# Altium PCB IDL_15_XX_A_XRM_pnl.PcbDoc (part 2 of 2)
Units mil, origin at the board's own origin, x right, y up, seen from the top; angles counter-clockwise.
Board outline 6130 x 3614.17 mil, 6 copper layers (Top Layer - SIG1, Layer 2 - GND1, Layer 3 - SIG2, Layer 4 - SIG3, Layer 5 - GND2, Bottom Layer - SIG4), stack 49.592 mil thick; 576 components, 385 nets, 1280 pads, 0 vias.
Unrouted connection lines stored in the file: 895.
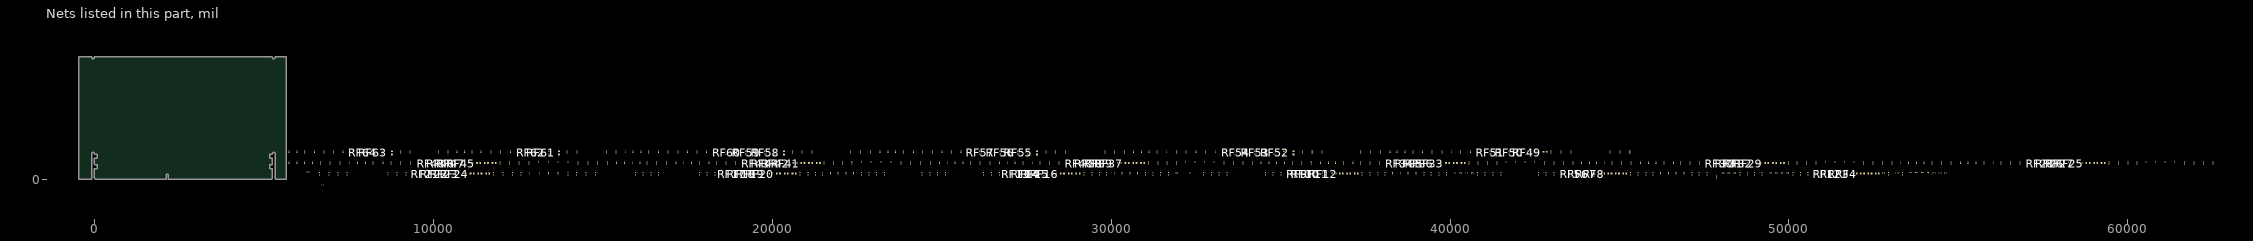
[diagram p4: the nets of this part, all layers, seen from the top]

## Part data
C1 C2 C3 C4 C13 C14 C15 C16 C17 C18 C19 C20 C21 C22 C23 C24 C33 C34 C35 C36 C37 C38 C39 C40 C41 C42 C43 C44 C53 C54 C55 C56 C57 C58 C59 C60 C61 C62 C63 C64 C73 C74 C75 C76 C77 C78 C79 C80 C81 C82 C83 C84 C93 C94 C95 C96 C97 C98 C99 C100 C101 C102 C103 C104 C113 C114 C115 C116 C117 C118 C119 C120 C121 C122 C123 C124 C133 C134 C135 C136 C137 C138 C139 C140 C141 C142 C143 C144 C153 C154 C155 C156 C157 C158 C159 C160 C161 C162 C163 C164 C173 C174 C175 C176 C177 C178 C179 C180 C181 C182 C183 C184 C193 C194 C195 C196 C197 C198 C199 C200 C201 C202 C203 C204 C213 C214 C215 C216 C217 C218 C219 C220 C221 C222 C223 C224 C233 C234 C235 C236 C237 C238 C239 C240 C241 C242 C243 C250 C251 C252 C253 C254 C255 C256 C257 C258 C265 C266 C267 C268 C269 C270 C271 C272 C273 C280 C281 C282 C283 C284 C285 C286 C287 C288 C295 C296 C297 C298 C299 C300 C301 C302 C307 C308 C309 C310 C311 C312 C317 C318 C319 C320: library part CAPCC0603_1_10N_50VX7R, "Capacitor chip ceramic 0603 50V X7R"
C5 C6 C7 C8 C25 C26 C27 C28 C45 C46 C47 C48 C65 C66 C67 C68 C85 C86 C87 C88 C105 C106 C107 C108 C125 C126 C127 C128 C145 C146 C147 C148 C165 C166 C167 C168 C185 C186 C187 C188 C205 C206 C207 C208 C225 C226 C227 C228 C244 C245 C246 C259 C260 C261 C274 C275 C276 C289 C290 C291 C303 C304 C313 C314: library part CAPCC0402_1_100N_50VX7R, "Capacitor chip ceramic 0402 50V X7R"
C9 C10 C11 C12 C29 C30 C31 C32 C49 C50 C51 C52 C69 C70 C71 C72 C89 C90 C91 C92 C109 C110 C111 C112 C129 C130 C131 C132 C149 C150 C151 C152 C169 C170 C171 C172 C189 C190 C191 C192 C209 C210 C211 C212 C229 C230 C231 C232 C247 C248 C249 C262 C263 C264 C277 C278 C279 C292 C293 C294 C305 C306 C315 C316: library part CAPCC0603_2_1U_50VX7R, "Capacitor chip ceramic 0603 50V X7R"
L1 L2 L3 L4 L9 L10 L11 L12 L17 L18 L19 L20 L25 L26 L27 L28 L33 L34 L35 L36 L41 L42 L43 L44 L49 L50 L51 L52 L57 L58 L59 L60 L65 L66 L67 L68 L73 L74 L75 L76 L81 L82 L83 L84 L89 L90 L91 L92 L97 L98 L99 L103 L104 L105 L109 L110 L111 L115 L116 L117 L121 L122 L125 L126: library part IND1008-1.5U_0.33A, "Chip inductor 1008 0.33A 2.3R"
L5 L6 L7 L8 L13 L14 L15 L16 L21 L22 L23 L24 L29 L30 L31 L32 L37 L38 L39 L40 L45 L46 L47 L48 L53 L54 L55 L56 L61 L62 L63 L64 L69 L70 L71 L72 L77 L78 L79 L80 L85 L86 L87 L88 L93 L94 L95 L96 L100 L101 L102 L106 L107 L108 L112 L113 L114 L118 L119 L120 L123 L124 L127 L128: library part IND0402-10.5N_1.0A, "Chip inductor 0402 1.0A 100mR"
R1 R2 R3 R4 R5 R6 R7 R8 R9 R10 R11 R12 R13 R14 R15 R16 R17 R18 R19 R20 R21 R22 R23 R24 R25 R26 R27 R28 R29 R30 R31 R32 R33 R34 R35 R36 R37 R38 R39 R40 R41 R42 R43 R44 R45 R46 R47 R48 R49 R50 R51 R52 R53 R54 R55 R56 R57 R58 R59 R60 R61 R62 R63 R64: library part RES0402-0-49.9R-1%100PPM, "Chip Resistor 0402 62.5mW 1% 100ppm"
RF1 RF2 RF3 RF4 RF5 RF6 RF7 RF8 RF9 RF10 RF11 RF12 RF13 RF14 RF15 RF16 RF17 RF18 RF19 RF20 RF21 RF22 RF23 RF24 RF25 RF26 RF27 RF28 RF29 RF30 RF31 RF32 RF33 RF34 RF35 RF36 RF37 RF38 RF39 RF40 RF41 RF42 RF43 RF44 RF45 RF46 RF47 RF48 RF49 RF50 RF51 RF52 RF53 RF54 RF55 RF56 RF57 RF58 RF59 RF60 RF61 RF62 RF63 RF64: "Monolithic Amplifier 50MHz - 4GHz, 0.75NF"

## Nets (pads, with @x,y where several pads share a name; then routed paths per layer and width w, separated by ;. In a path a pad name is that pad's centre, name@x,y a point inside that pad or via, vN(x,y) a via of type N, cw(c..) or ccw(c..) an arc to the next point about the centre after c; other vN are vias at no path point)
GND: C1.2 C2.2 C3.2 C4.2 C5.2 C6.2 C7.2 C8.2 C9.2 C10.2 C11.2 C12.2 C21.2 C22.2 C23.2 C24.2 C25.2 C26.2 C27.2 C28.2 C29.2 C30.2 C31.2 C32.2 C41.2 C42.2 C43.2 C44.2 C45.2 C46.2 C47.2 C48.2 C49.2 C50.2 C51.2 C52.2 C61.2 C62.2 C63.2 C64.2 C65.2 C66.2 C67.2 C68.2 C69.2 C70.2 C71.2 C72.2 C81.2 C82.2 C83.2 C84.2 C85.2 C86.2 C87.2 C88.2 C89.2 C90.2 C91.2 C92.2 C101.2 C102.2 C103.2 C104.2 C105.2 C106.2 C107.2 C108.2 C109.2 C110.2 C111.2 C112.2 C121.2 C122.2 C123.2 C124.2 C125.2 C126.2 C127.2 C128.2 C129.2 C130.2 C131.2 C132.2 C141.2 C142.2 C143.2 C144.2 C145.2 C146.2 C147.2 C148.2 C149.2 C150.2 C151.2 C152.2 C161.2 C162.2 C163.2 C164.2 C165.2 C166.2 C167.2 C168.2 C169.2 C170.2 C171.2 C172.2 C181.2 C182.2 C183.2 C184.2 C185.2 C186.2 C187.2 C188.2 C189.2 C190.2 C191.2 C192.2 C201.2 C202.2 C203.2 C204.2 C205.2 C206.2 C207.2 C208.2 C209.2 C210.2 C211.2 C212.2 C221.2 C222.2 C223.2 C224.2 C225.2 C226.2 C227.2 C228.2 C229.2 C230.2 C231.2 C232.2 C241.2 C242.2 C243.2 C244.2 C245.2 C246.2 C247.2 C248.2 C249.2 C256.2 C257.2 C258.2 C259.2 C260.2 C261.2 C262.2 C263.2 C264.2 C271.2 C272.2 C273.2 C274.2 C275.2 C276.2 C277.2 C278.2 C279.2 C286.2 C287.2 C288.2 C289.2 C290.2 C291.2 C292.2 C293.2 C294.2 C301.2 C302.2 C303.2 C304.2 C305.2 C306.2 C311.2 C312.2 C313.2 C314.2 C315.2 C316.2 R1.1 R2.1 R3.1 R4.1 R5.1 R6.1 R7.1 R8.1 R9.1 R10.1 R11.1 R12.1 R13.1 R14.1 R15.1 R16.1 R17.1 R18.1 R19.1 R20.1 R21.1 R22.1 R23.1 R24.1 R25.1 R26.1 R27.1 R28.1 R29.1 R30.1 R31.1 R32.1 R33.1 R34.1 R35.1 R36.1 R37.1 R38.1 R39.1 R40.1 R41.1 R42.1 R43.1 R44.1 R45.1 R46.1 R47.1 R48.1 R49.1 R50.1 R51.1 R52.1 R53.1 R54.1 R55.1 R56.1 R57.1 R58.1 R59.1 R60.1 R61.1 R62.1 R63.1 R64.1 RF1.2 RF1.4 RF2.2 RF2.4 RF3.2 RF3.4 RF4.2 RF4.4 RF5.2 RF5.4 RF6.2 RF6.4 RF7.2 RF7.4 RF8.2 RF8.4 RF9.2 RF9.4 RF10.2 RF10.4 RF11.2 RF11.4 RF12.2 RF12.4 RF13.2 RF13.4 RF14.2 RF14.4 RF15.2 RF15.4 RF16.2 RF16.4 RF17.2 RF17.4 RF18.2 RF18.4 RF19.2 RF19.4 RF20.2 RF20.4 RF21.2 RF21.4 RF22.2 RF22.4 RF23.2 RF23.4 RF24.2 RF24.4 RF25.2 RF25.4 RF26.2 RF26.4 RF27.2 RF27.4 RF28.2 RF28.4 RF29.2 RF29.4 RF30.2 RF30.4 RF31.2 RF31.4 RF32.2 RF32.4 RF33.2 RF33.4 RF34.2 RF34.4 RF35.2 RF35.4 RF36.2 RF36.4 RF37.2 RF37.4 RF38.2 RF38.4 RF39.2 RF39.4 RF40.2 RF40.4 RF41.2 RF41.4 RF42.2 RF42.4 RF43.2 RF43.4 RF44.2 RF44.4 RF45.2 RF45.4 RF46.2 RF46.4 RF47.2 RF47.4 RF48.2 RF48.4 RF49.2 RF49.4 RF50.2 RF50.4 RF51.2 RF51.4 RF52.2 RF52.4 RF53.2 RF53.4 RF54.2 RF54.4 RF55.2 RF55.4 RF56.2 RF56.4 RF57.2 RF57.4 RF58.2 RF58.4 RF59.2 RF59.4 RF60.2 RF60.4 RF61.2 RF61.4 RF62.2 RF62.4 RF63.2 RF63.4 RF64.2 RF64.4
NetC1_1: C1.1 C5.1 C9.1 L1.2
NetC2_1: C2.1 C6.1 C10.1 L2.2
NetC3_1: C3.1 C7.1 C11.1 L3.2
NetC4_1: C4.1 C8.1 C12.1 L4.2
NetC13_1: C13.1 L1.1 RF1.1
NetC13_2: C13.2 L5.1
NetC14_1: C14.1 L2.1 RF2.1
NetC14_2: C14.2 L6.1
NetC15_1: C15.1 L3.1 RF3.1
NetC15_2: C15.2 L7.1
NetC16_1: C16.1 L4.1 RF4.1
NetC16_2: C16.2 L8.1
NetC17_2: C17.2 RF1.3
NetC18_2: C18.2 RF2.3
NetC19_2: C19.2 RF3.3
NetC20_2: C20.2 RF4.3
NetC21_1: C21.1 C25.1 C29.1 L9.2
NetC22_1: C22.1 C26.1 C30.1 L10.2
NetC23_1: C23.1 C27.1 C31.1 L11.2
NetC24_1: C24.1 C28.1 C32.1 L12.2
NetC33_1: C33.1 L9.1 RF5.1
NetC33_2: C33.2 L13.1
NetC34_1: C34.1 L10.1 RF6.1
NetC34_2: C34.2 L14.1
NetC35_1: C35.1 L11.1 RF7.1
NetC35_2: C35.2 L15.1
NetC36_1: C36.1 L12.1 RF8.1
NetC36_2: C36.2 L16.1
NetC37_2: C37.2 RF5.3
NetC38_2: C38.2 RF6.3
NetC39_2: C39.2 RF7.3
NetC40_2: C40.2 RF8.3
NetC41_1: C41.1 C45.1 C49.1 L17.2
NetC42_1: C42.1 C46.1 C50.1 L18.2
NetC43_1: C43.1 C47.1 C51.1 L19.2
NetC44_1: C44.1 C48.1 C52.1 L20.2
NetC53_1: C53.1 L17.1 RF9.1
NetC53_2: C53.2 L21.1
NetC54_1: C54.1 L18.1 RF10.1
NetC54_2: C54.2 L22.1
NetC55_1: C55.1 L19.1 RF11.1
NetC55_2: C55.2 L23.1
NetC56_1: C56.1 L20.1 RF12.1
NetC56_2: C56.2 L24.1
NetC57_2: C57.2 RF9.3
NetC58_2: C58.2 RF10.3
NetC59_2: C59.2 RF11.3
NetC60_2: C60.2 RF12.3
NetC61_1: C61.1 C65.1 C69.1 L25.2
NetC62_1: C62.1 C66.1 C70.1 L26.2
NetC63_1: C63.1 C67.1 C71.1 L27.2
NetC64_1: C64.1 C68.1 C72.1 L28.2
NetC73_1: C73.1 L25.1 RF13.1
NetC73_2: C73.2 L29.1
NetC74_1: C74.1 L26.1 RF14.1
NetC74_2: C74.2 L30.1
NetC75_1: C75.1 L27.1 RF15.1
NetC75_2: C75.2 L31.1
NetC76_1: C76.1 L28.1 RF16.1
NetC76_2: C76.2 L32.1
NetC77_2: C77.2 RF13.3
NetC78_2: C78.2 RF14.3
NetC79_2: C79.2 RF15.3
NetC80_2: C80.2 RF16.3
NetC81_1: C81.1 C85.1 C89.1 L33.2
NetC82_1: C82.1 C86.1 C90.1 L34.2
NetC83_1: C83.1 C87.1 C91.1 L35.2
NetC84_1: C84.1 C88.1 C92.1 L36.2
NetC93_1: C93.1 L33.1 RF17.1
NetC93_2: C93.2 L37.1
NetC94_1: C94.1 L34.1 RF18.1
NetC94_2: C94.2 L38.1
NetC95_1: C95.1 L35.1 RF19.1
NetC95_2: C95.2 L39.1
NetC96_1: C96.1 L36.1 RF20.1
NetC96_2: C96.2 L40.1
NetC97_2: C97.2 RF17.3
NetC98_2: C98.2 RF18.3
NetC99_2: C99.2 RF19.3
NetC100_2: C100.2 RF20.3
NetC101_1: C101.1 C105.1 C109.1 L41.2
NetC102_1: C102.1 C106.1 C110.1 L42.2
NetC103_1: C103.1 C107.1 C111.1 L43.2
NetC104_1: C104.1 C108.1 C112.1 L44.2
NetC113_1: C113.1 L41.1 RF21.1
NetC113_2: C113.2 L45.1
NetC114_1: C114.1 L42.1 RF22.1
NetC114_2: C114.2 L46.1
NetC115_1: C115.1 L43.1 RF23.1
NetC115_2: C115.2 L47.1
NetC116_1: C116.1 L44.1 RF24.1
NetC116_2: C116.2 L48.1
NetC117_2: C117.2 RF21.3
NetC118_2: C118.2 RF22.3
NetC119_2: C119.2 RF23.3
NetC120_2: C120.2 RF24.3
NetC121_1: C121.1 C125.1 C129.1 L49.2
NetC122_1: C122.1 C126.1 C130.1 L50.2
NetC123_1: C123.1 C127.1 C131.1 L51.2
NetC124_1: C124.1 C128.1 C132.1 L52.2
NetC133_1: C133.1 L49.1 RF25.1
NetC133_2: C133.2 L53.1
NetC134_1: C134.1 L50.1 RF26.1
NetC134_2: C134.2 L54.1
NetC135_1: C135.1 L51.1 RF27.1
NetC135_2: C135.2 L55.1
NetC136_1: C136.1 L52.1 RF28.1
NetC136_2: C136.2 L56.1
NetC137_2: C137.2 RF25.3
NetC138_2: C138.2 RF26.3
NetC139_2: C139.2 RF27.3
NetC140_2: C140.2 RF28.3
NetC141_1: C141.1 C145.1 C149.1 L57.2
NetC142_1: C142.1 C146.1 C150.1 L58.2
NetC143_1: C143.1 C147.1 C151.1 L59.2
NetC144_1: C144.1 C148.1 C152.1 L60.2
NetC153_1: C153.1 L57.1 RF29.1
NetC153_2: C153.2 L61.1
NetC154_1: C154.1 L58.1 RF30.1
NetC154_2: C154.2 L62.1
NetC155_1: C155.1 L59.1 RF31.1
NetC155_2: C155.2 L63.1
NetC156_1: C156.1 L60.1 RF32.1
NetC156_2: C156.2 L64.1
NetC157_2: C157.2 RF29.3
NetC158_2: C158.2 RF30.3
NetC159_2: C159.2 RF31.3
NetC160_2: C160.2 RF32.3
NetC161_1: C161.1 C165.1 C169.1 L65.2
NetC162_1: C162.1 C166.1 C170.1 L66.2
NetC163_1: C163.1 C167.1 C171.1 L67.2
NetC164_1: C164.1 C168.1 C172.1 L68.2
NetC173_1: C173.1 L65.1 RF33.1
NetC173_2: C173.2 L69.1
NetC174_1: C174.1 L66.1 RF34.1
NetC174_2: C174.2 L70.1
NetC175_1: C175.1 L67.1 RF35.1
NetC175_2: C175.2 L71.1
NetC176_1: C176.1 L68.1 RF36.1
NetC176_2: C176.2 L72.1
NetC177_2: C177.2 RF33.3
NetC178_2: C178.2 RF34.3
NetC179_2: C179.2 RF35.3
NetC180_2: C180.2 RF36.3
NetC181_1: C181.1 C185.1 C189.1 L73.2
NetC182_1: C182.1 C186.1 C190.1 L74.2
NetC183_1: C183.1 C187.1 C191.1 L75.2
NetC184_1: C184.1 C188.1 C192.1 L76.2
NetC193_1: C193.1 L73.1 RF37.1
NetC193_2: C193.2 L77.1
NetC194_1: C194.1 L74.1 RF38.1
NetC194_2: C194.2 L78.1
NetC195_1: C195.1 L75.1 RF39.1
NetC195_2: C195.2 L79.1
NetC196_1: C196.1 L76.1 RF40.1
NetC196_2: C196.2 L80.1
NetC197_2: C197.2 RF37.3
NetC198_2: C198.2 RF38.3
NetC199_2: C199.2 RF39.3
NetC200_2: C200.2 RF40.3
NetC201_1: C201.1 C205.1 C209.1 L81.2
NetC202_1: C202.1 C206.1 C210.1 L82.2
NetC203_1: C203.1 C207.1 C211.1 L83.2
NetC204_1: C204.1 C208.1 C212.1 L84.2
NetC213_1: C213.1 L81.1 RF41.1
NetC213_2: C213.2 L85.1
NetC214_1: C214.1 L82.1 RF42.1
NetC214_2: C214.2 L86.1
NetC215_1: C215.1 L83.1 RF43.1
NetC215_2: C215.2 L87.1
NetC216_1: C216.1 L84.1 RF44.1
NetC216_2: C216.2 L88.1
NetC217_2: C217.2 RF41.3
NetC218_2: C218.2 RF42.3
NetC219_2: C219.2 RF43.3
NetC220_2: C220.2 RF44.3
NetC221_1: C221.1 C225.1 C229.1 L89.2
NetC222_1: C222.1 C226.1 C230.1 L90.2
NetC223_1: C223.1 C227.1 C231.1 L91.2
NetC224_1: C224.1 C228.1 C232.1 L92.2
NetC233_1: C233.1 L89.1 RF45.1
NetC233_2: C233.2 L93.1
NetC234_1: C234.1 L90.1 RF46.1
NetC234_2: C234.2 L94.1
NetC235_1: C235.1 L91.1 RF47.1
NetC235_2: C235.2 L95.1
NetC236_1: C236.1 L92.1 RF48.1
NetC236_2: C236.2 L96.1
NetC237_2: C237.2 RF45.3
NetC238_2: C238.2 RF46.3
NetC239_2: C239.2 RF47.3
NetC240_2: C240.2 RF48.3
NetC241_1: C241.1 C244.1 C247.1 L97.2
NetC242_1: C242.1 C245.1 C248.1 L98.2
NetC243_1: C243.1 C246.1 C249.1 L99.2
NetC250_1: C250.1 L97.1 RF49.1
NetC250_2: C250.2 L100.1
NetC251_1: C251.1 L98.1 RF50.1
NetC251_2: C251.2 L101.1
NetC252_2: C252.2 RF49.3
NetC253_1: C253.1 L99.1 RF51.1
NetC253_2: C253.2 L102.1
NetC254_2: C254.2 RF50.3
NetC255_2: C255.2 RF51.3
NetC256_1: C256.1 C259.1 C262.1 L103.2
NetC257_1: C257.1 C260.1 C263.1 L104.2
NetC258_1: C258.1 C261.1 C264.1 L105.2
NetC265_1: C265.1 L103.1 RF52.1
NetC265_2: C265.2 L106.1
NetC266_1: C266.1 L104.1 RF53.1
NetC266_2: C266.2 L107.1
NetC267_2: C267.2 RF52.3
NetC268_1: C268.1 L105.1 RF54.1
NetC268_2: C268.2 L108.1
NetC269_2: C269.2 RF53.3
NetC270_2: C270.2 RF54.3
NetC271_1: C271.1 C274.1 C277.1 L109.2
NetC272_1: C272.1 C275.1 C278.1 L110.2
NetC273_1: C273.1 C276.1 C279.1 L111.2
NetC280_1: C280.1 L109.1 RF55.1
NetC280_2: C280.2 L112.1
NetC281_1: C281.1 L110.1 RF56.1
NetC281_2: C281.2 L113.1
NetC282_2: C282.2 RF55.3
NetC283_1: C283.1 L111.1 RF57.1
NetC283_2: C283.2 L114.1
NetC284_2: C284.2 RF56.3
NetC285_2: C285.2 RF57.3
NetC286_1: C286.1 C289.1 C292.1 L115.2
NetC287_1: C287.1 C290.1 C293.1 L116.2
NetC288_1: C288.1 C291.1 C294.1 L117.2
NetC295_1: C295.1 L115.1 RF58.1
NetC295_2: C295.2 L118.1
NetC296_1: C296.1 L116.1 RF59.1
NetC296_2: C296.2 L119.1
NetC297_2: C297.2 RF58.3
NetC298_1: C298.1 L117.1 RF60.1
NetC298_2: C298.2 L120.1
NetC299_2: C299.2 RF59.3
NetC300_2: C300.2 RF60.3
NetC301_1: C301.1 C303.1 C305.1 L121.2
NetC302_1: C302.1 C304.1 C306.1 L122.2
NetC307_1: C307.1 L121.1 RF61.1
NetC307_2: C307.2 L123.1
NetC308_1: C308.1 L122.1 RF62.1
NetC308_2: C308.2 L124.1
NetC309_2: C309.2 RF61.3
NetC310_2: C310.2 RF62.3
NetC311_1: C311.1 C313.1 C315.1 L125.2
NetC312_1: C312.1 C314.1 C316.1 L126.2
NetC317_1: C317.1 L125.1 RF63.1
NetC317_2: C317.2 L127.1
NetC318_1: C318.1 L126.1 RF64.1
NetC318_2: C318.2 L128.1
NetC319_2: C319.2 RF63.3
NetC320_2: C320.2 RF64.3
RF1: C17.1 R1.2
RF2: C37.1 R5.2
RF3: C57.1 R9.2
RF4: C77.1 R13.2
RF5: C97.1 R17.2
RF6: C117.1 R21.2
RF7: C18.1 R2.2
RF8: C38.1 R6.2
RF9: C58.1 R10.2
RF10: C78.1 R14.2
RF11: C98.1 R18.2
RF12: C118.1 R22.2
RF13: C19.1 R3.2
RF14: C39.1 R7.2
RF15: C59.1 R11.2
RF16: C79.1 R15.2
RF17: C99.1 R19.2
RF18: C119.1 R23.2
RF19: C20.1 R4.2
RF20: C40.1 R8.2
RF21: C60.1 R12.2
RF22: C80.1 R16.2
RF23: C100.1 R20.2
RF24: C120.1 R24.2
RF25: C138.1 R26.2
RF26: C158.1 R30.2
RF27: C178.1 R34.2
RF28: C198.1 R38.2
RF29: C218.1 R42.2
RF30: C238.1 R46.2
RF31: C139.1 R27.2
RF32: C159.1 R31.2
RF33: C179.1 R35.2
RF34: C199.1 R39.2
RF35: C219.1 R43.2
RF36: C239.1 R47.2
RF37: C137.1 R25.2
RF38: C157.1 R29.2
RF39: C177.1 R33.2
RF40: C197.1 R37.2
RF41: C217.1 R41.2
RF42: C237.1 R45.2
RF43: C140.1 R28.2
RF44: C160.1 R32.2
RF45: C180.1 R36.2
RF46: C200.1 R40.2
RF47: C220.1 R44.2
RF48: C240.1 R48.2
RF49: C254.1 R50.2
RF50: C269.1 R53.2
RF51: C284.1 R56.2
RF52: C299.1 R59.2
RF53: C309.1 R61.2
RF54: C319.1 R63.2
RF55: C255.1 R51.2
RF56: C270.1 R54.2
RF57: C285.1 R57.2
RF58: C300.1 R60.2
RF59: C310.1 R62.2
RF60: C320.1 R64.2
RF61: C252.1 R49.2
RF62: C267.1 R52.2
RF63: C282.1 R55.2
RF64: C297.1 R58.2
RF-OUT1: L5.2
RF-OUT2: L13.2
RF-OUT3: L21.2
RF-OUT4: L29.2
RF-OUT5: L37.2
RF-OUT6: L45.2
RF-OUT7: L6.2
RF-OUT8: L14.2
RF-OUT9: L22.2
RF-OUT10: L30.2
RF-OUT11: L38.2
RF-OUT12: L46.2
RF-OUT13: L7.2
RF-OUT14: L15.2
RF-OUT15: L23.2
RF-OUT16: L31.2
RF-OUT17: L39.2
RF-OUT18: L47.2
RF-OUT19: L8.2
RF-OUT20: L16.2
RF-OUT21: L24.2
RF-OUT22: L32.2
RF-OUT23: L40.2
RF-OUT24: L48.2
RF-OUT25: L54.2
RF-OUT26: L62.2
RF-OUT27: L70.2
RF-OUT28: L78.2
RF-OUT29: L86.2
RF-OUT30: L94.2
RF-OUT31: L55.2
RF-OUT32: L63.2
RF-OUT33: L71.2
RF-OUT34: L79.2
RF-OUT35: L87.2
RF-OUT36: L95.2
RF-OUT37: L53.2
RF-OUT38: L61.2
RF-OUT39: L69.2
RF-OUT40: L77.2
RF-OUT41: L85.2
RF-OUT42: L93.2
RF-OUT43: L56.2
RF-OUT44: L64.2
RF-OUT45: L72.2
RF-OUT46: L80.2
RF-OUT47: L88.2
RF-OUT48: L96.2
RF-OUT49: L101.2
RF-OUT50: L107.2
RF-OUT51: L113.2
RF-OUT52: L119.2
RF-OUT53: L123.2
RF-OUT54: L127.2
RF-OUT55: L102.2
RF-OUT56: L108.2
RF-OUT57: L114.2
RF-OUT58: L120.2
RF-OUT59: L124.2
RF-OUT60: L128.2
RF-OUT61: L100.2
RF-OUT62: L106.2
RF-OUT63: L112.2
RF-OUT64: L118.2

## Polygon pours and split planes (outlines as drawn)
no net on Layer 2 - GND1 (split plane): 7.54,1787.81 22.49,1827.69
no net on Layer 2 - GND1 (split plane): 625 vertices, not listed, extent -444.9,20.1 5644.9,3594.08
no net on Layer 5 - GND2 (split plane): 7.54,1787.81 22.49,1827.69
no net on Layer 5 - GND2 (split plane): 625 vertices, not listed, extent -444.9,20.1 5644.9,3594.08

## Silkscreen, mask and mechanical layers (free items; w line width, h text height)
Board Outline:
  lines w3.94: 0,2598.43 ccw(c11.81,2598.43) 11.81,2586.61 62.99,2586.61 cw(c62.99,2566.93) 82.68,2566.93 82.68,2488.19 cw(c62.99,2488.19) 62.99,2468.5 11.81,2468.5 ccw(c11.81,2456.69) 0,2456.69 0,2291.34 ccw(c11.81,2291.34) 11.81,2279.53 62.99,2279.53 cw(c62.99,2259.84) 82.68,2259.84 82.68,2181.1 cw(c62.99,2181.1) 62.99,2161.42 11.81,2161.42 ccw(c11.81,2149.61) 0,2149.61 0,1875.98 29.53,1846.46 2115.16,1846.46 ccw(c2115.16,1854.33) 2123.03,1854.33 2123.03,1966.54 cw(c2152.56,1966.54) 2152.56,1996.06 cw(c2152.56,1966.54) 2182.09,1966.54 2182.09,1854.33 ccw(c2189.96,1854.33) 2189.96,1846.46 5220.47,1846.46 5250,1875.98 5250,2149.61 ccw(c5238.19,2149.61) 5238.19,2161.42 5187.01,2161.42 cw(c5187.01,2181.1) 5167.32,2181.1 5167.32,2259.84 cw(c5187.01,2259.84) 5187.01,2279.53 5238.19,2279.53 ccw(c5238.19,2291.34) 5250,2291.34 5250,2456.69 ccw(c5238.19,2456.69) 5238.19,2468.5 5187.01,2468.5 cw(c5187.01,2488.19) 5167.32,2488.19 5167.32,2566.93 cw(c5187.01,2566.93) 5187.01,2586.61 5238.19,2586.61 ccw(c5238.19,2598.43) 5250,2598.43 ; 0,2598.43 ccw(c-39.37,2598.43) -39.37,2637.8 ccw(c-39.37,2598.43) -78.74,2598.43 -78.74,1748.03 ccw(c-39.37,1748.03) -39.37,1708.66 ccw(c-39.37,1748.03) 0,1748.03 0,1767.72 5250,1767.72 5250,1748.03 ccw(c5289.37,1748.03) 5289.37,1708.66 ccw(c5289.37,1748.03) 5328.74,1748.03 5328.74,2598.43 ccw(c5289.37,2598.43) 5289.37,2637.8 ccw(c5289.37,2598.43) 5250,2598.43 ; 0,2598.43 0,2598.43 ; 5250,2598.43 5250,2598.43 ; -465,0 -465,3614 -78.74,3614 -78.74,3594.49 ccw(c-39.37,3594.49) -39.37,3555.12 ccw(c-39.37,3594.49) 0,3594.49 0,3614.17 5250,3614.17 5250,3594.49 ccw(c5289.37,3594.49) 5289.37,3555.12 ccw(c5289.37,3594.49) 5328.74,3594.49 5328.74,3614 5665,3614 5665,0 5328.74,0 5328.74,751.97 ccw(c5289.37,751.97) 5289.37,791.34 ccw(c5289.37,751.97) 5250,751.97 cw(c5238.19,751.97) 5238.19,740.16 5187.01,740.16 ccw(c5187.01,720.47) 5167.32,720.47 5167.32,641.73 ccw(c5187.01,641.73) 5187.01,622.05 5238.19,622.05 cw(c5238.19,610.24) 5250,610.24 5250,444.88 cw(c5238.19,444.88) 5238.19,433.07 5187.01,433.07 ccw(c5187.01,413.39) 5167.32,413.39 5167.32,334.65 ccw(c5187.01,334.65) 5187.01,314.96 5238.19,314.96 cw(c5238.19,303.15) 5250,303.15 5250,29.53 5220.47,0 2189.96,0 cw(c2189.96,7.87) 2182.09,7.87 2182.09,120.08 ccw(c2152.56,120.08) 2152.56,149.61 ccw(c2152.56,120.08) 2123.03,120.08 2123.03,7.87 cw(c2115.16,7.87) 2115.16,0 29.53,0 0,29.53 0,303.15 cw(c11.81,303.15) 11.81,314.96 62.99,314.96 ccw(c62.99,334.65) 82.68,334.65 82.68,413.39 ccw(c62.99,413.39) 62.99,433.07 11.81,433.07 cw(c11.81,444.88) 0,444.88 0,610.24 cw(c11.81,610.24) 11.81,622.05 62.99,622.05 ccw(c62.99,641.73) 82.68,641.73 82.68,720.47 ccw(c62.99,720.47) 62.99,740.16 11.81,740.16 cw(c11.81,751.97) 0,751.97 ccw(c-39.37,751.97) -39.37,791.34 ccw(c-39.37,751.97) -78.74,751.97 -78.74,0 -465,0 ; -78.74,933.07 ccw(c-39.37,933.07) -39.37,893.7 ccw(c-39.37,933.07) 0,933.07 0,1566.93 ccw(c-39.37,1566.93) -39.37,1606.3 ccw(c-39.37,1566.93) -78.74,1566.93 -78.74,933.07 ; -78.74,2779.53 ccw(c-39.37,2779.53) -39.37,2740.16 ccw(c-39.37,2779.53) 0,2779.53 0,3413.39 ccw(c-39.37,3413.39) -39.37,3452.76 ccw(c-39.37,3413.39) -78.74,3413.39 -78.74,2779.53 ; 5250,933.07 ccw(c5289.37,933.07) 5289.37,893.7 ccw(c5289.37,933.07) 5328.74,933.07 5328.74,1566.93 ccw(c5289.37,1566.93) 5289.37,1606.3 ccw(c5289.37,1566.93) 5250,1566.93 5250,933.07 ; 5250,2779.53 ccw(c5289.37,2779.53) 5289.37,2740.16 ccw(c5289.37,2779.53) 5328.74,2779.53 5328.74,3413.39 ccw(c5289.37,3413.39) 5289.37,3452.76 ccw(c5289.37,3413.39) 5250,3413.39 5250,2779.53
Panel_Fid:
  circle w26.38: c165.35,2059.06 r11.81
  circle w26.38: c5086.61,3539.37 r11.81
  circle w26.38: c5086.61,1692.91 r11.81
  circle w26.38: c165.35,212.6 r11.81
Panel_StCTop:
  lines w3.94: 130.91,2123.03 130.91,3706.69 652.56,4228.35 ; 191.93,217.52 790.3,-957.46 ; 3854.33,-944.88 4855.32,56.1 4855.32,1453.74 5000.98,1599.41 ; 3957.68,4195.87 5008.86,3644.68
  text "Engraved on bottom side of top paste stencil (GTP)" at 898.62,4220.47 h59.06
  text "Engraved on bottom side of top paste stencil (GTP)" at 950.79,-1034.45 h59.06
  text "Stencil appertures are NOT reduced!" at 1358.46,-2985.83 h78.74
  text "View from top side!" at 1362.4,-3135.44 h78.74
  text ".IDLnum" at 11864.45,-3904.02 h160
  text "STENCIL" at 10844.49,-3980.31 h100
  text ".ProjectName2" at 11864.45,-4084.02 h160
Panel_StCBot:
  text "Stencil appertures are NOT reduced!" at 1358.46,-2985.83 h78.74
  text "View from top side!" at 1362.4,-3135.44 h78.74
  text ".IDLnum" at 11864.45,-3904.02 h160
  text "STENCIL" at 10844.49,-3980.31 h100
  text ".ProjectName2" at 11864.45,-4084.02 h160
Panel_Comm:
  text "Milled with 2.0mm mill" at 1361.22,-2769.68 h100
  text ".IDLnum" at 11864.45,-3904.02 h160
  text "PANEL" at 10844.49,-3980.31 h100
  text ".ProjectName2" at 11864.45,-4084.02 h160
Panel_Sheet Top:
  lines w3.9: -2290.55,-2660.68 -2190.55,-2660.68 ; -2290.55,-747.35 -2190.55,-747.35 ; -2290.55,1165.98 -2190.55,1165.98 ; -2290.55,3079.32 -2190.55,3079.32 ; -2290.55,4992.65 -2190.55,4992.65 ; -315.55,-4574.02 -315.55,-4474.02 ; -315.55,6805.98 -315.55,6905.98 ; 1659.45,-4574.02 1659.45,-4474.02 ; 1659.45,6805.98 1659.45,6905.98 ; 3634.45,-4574.02 3634.45,-4474.02 ; 3634.45,6805.98 3634.45,6905.98 ; 5609.45,-4574.02 5609.45,-4474.02 ; 5609.45,6805.98 5609.45,6905.98 ; 7584.45,-4574.02 7584.45,-4474.02 ; 7584.45,6805.98 7584.45,6905.98 ; 9559.45,-4574.02 9559.45,-4474.02 ; 9559.45,6805.98 9559.45,6905.98 ; 11534.45,-4574.02 11534.45,-4474.02 ; 11534.45,6805.98 11534.45,6905.98 ; 13409.45,-2660.68 13509.45,-2660.68 ; 13409.45,-747.35 13509.45,-747.35 ; 13409.45,1165.98 13509.45,1165.98 ; 13409.45,3079.32 13509.45,3079.32 ; 13409.45,4992.65 13509.45,4992.65 ; -2290.55,-4573.92 13509.36,-4573.92 13509.36,6905.98 -2290.55,6905.98 -2290.55,-4573.92 ; -2190.29,-4474.21 13409.1,-4474.21 13409.1,6806.28 -2190.29,6806.28 -2190.29,-4474.21
  lines w3.94: 6719.45,-4474.21 6719.45,-3764.02 13409.1,-3764.02 ; 6719.45,-4123.25 13409.45,-4123.25 ; 6719.45,-4004.02 11539.45,-4004.02 ; 6719.45,-3884.02 11539.45,-3884.02 ; 8224.45,-4123.25 8224.45,-3764.02 ; 9224.45,-4123.25 9224.45,-3764.02 ; 10814.45,-4123.25 10814.45,-3764.02 ; 11539.45,-4474.21 11539.45,-3764.02 ; 11539.45,-3944.02 13409.1,-3944.02
  text "1" at -1323.23,6826.47 h60
  text "2" at 651.77,6826.47 h60
  text "3" at 2626.77,6826.47 h60
  text "4" at 4601.77,6826.47 h60
  text "5" at 6576.77,6826.47 h60
  text "6" at 8551.77,6826.47 h60
  text "7" at 10526.77,6826.47 h60
  text "8" at 12501.77,6826.47 h60
  text "A" at -2265.77,5869.32 h60
  text "A" at 13434.23,5869.32 h60
  text "B" at -2265.77,3955.98 h60
  text "B" at 13434.23,3955.98 h60
  text "C" at -2270.82,2042.65 h60
  text "C" at 13429.18,2042.65 h60
  text "D" at -2270.82,129.32 h60
  text "D" at 13429.18,129.32 h60
  text "E" at -2265.77,-1784.02 h60
  text "E" at 13434.23,-1784.02 h60
  text "F" at -2265.77,-3697.35 h60
  text "F" at 13434.23,-3697.35 h60
  text "Designer:" at 6744.45,-3854.02 h100
  text ".Designer" at 7309.45,-3859.02 h100
  text "Version:" at 8249.45,-3859.02 h100
  text ".Version" at 8809.45,-3859.02 h100
  text "File:" at 9249.45,-3859.02 h100
  text ".Pcb_File_Name_No_Path" at 9449.45,-3859.02 h100
  text "Sheet  1 of  1" at 10844.45,-3859.02 h100
  text "Code:" at 11564.45,-3904.02 h100
  text "Drawn By:" at 6744.45,-3974.02 h100
  text ".Drawn_By" at 7309.45,-3974.02 h100
  text "Modif. Date:" at 8249.45,-3979.02 h100
  text "(Date)" at 8754.45,-3979.02 h100
  text "Variant:" at 9249.45,-3979.02 h100
  text ".VariantName" at 9614.45,-3979.02 h100
  text "ID:" at 11569.45,-4084.02 h100
  text "Approved By:" at 6744.45,-4094.02 h100
  text ".Approved_By" at 7309.45,-4094.02 h100
  text "Print Date:" at 8249.45,-4099.02 h100
  text ".Print_Date" at 8754.45,-4099.02 h100
  text "Signature:" at 9249.45,-4099.02 h100
  text "Size:  A3 H" at 10844.45,-4099.02 h100
  text "Title:" at 6744.45,-4224.02 h100
  text "University of Hawaii at Manoa" at 11570.87,-4232.28 h100
  text "High Energy Physics Group" at 11570.87,-4330.71 h100
  text ".Printout_Name" at 6969.45,-4364.02 h160
  text "Instrumentation Development Laboratory" at 11570.87,-4433.07 h100
  text "1" at -1323.23,-4553.53 h60
  text "2" at 651.77,-4553.53 h60
  text "3" at 2626.77,-4553.53 h60
  text "4" at 4601.77,-4553.53 h60
  text "5" at 6576.77,-4553.53 h60
  text "6" at 8551.77,-4553.53 h60
  text "7" at 10526.77,-4553.53 h60
  text "8" at 12501.77,-4553.53 h60

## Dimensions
-465,3614 to 5665,3614 on Mech 16
5665,3614 to 5665,0 on Mech 16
